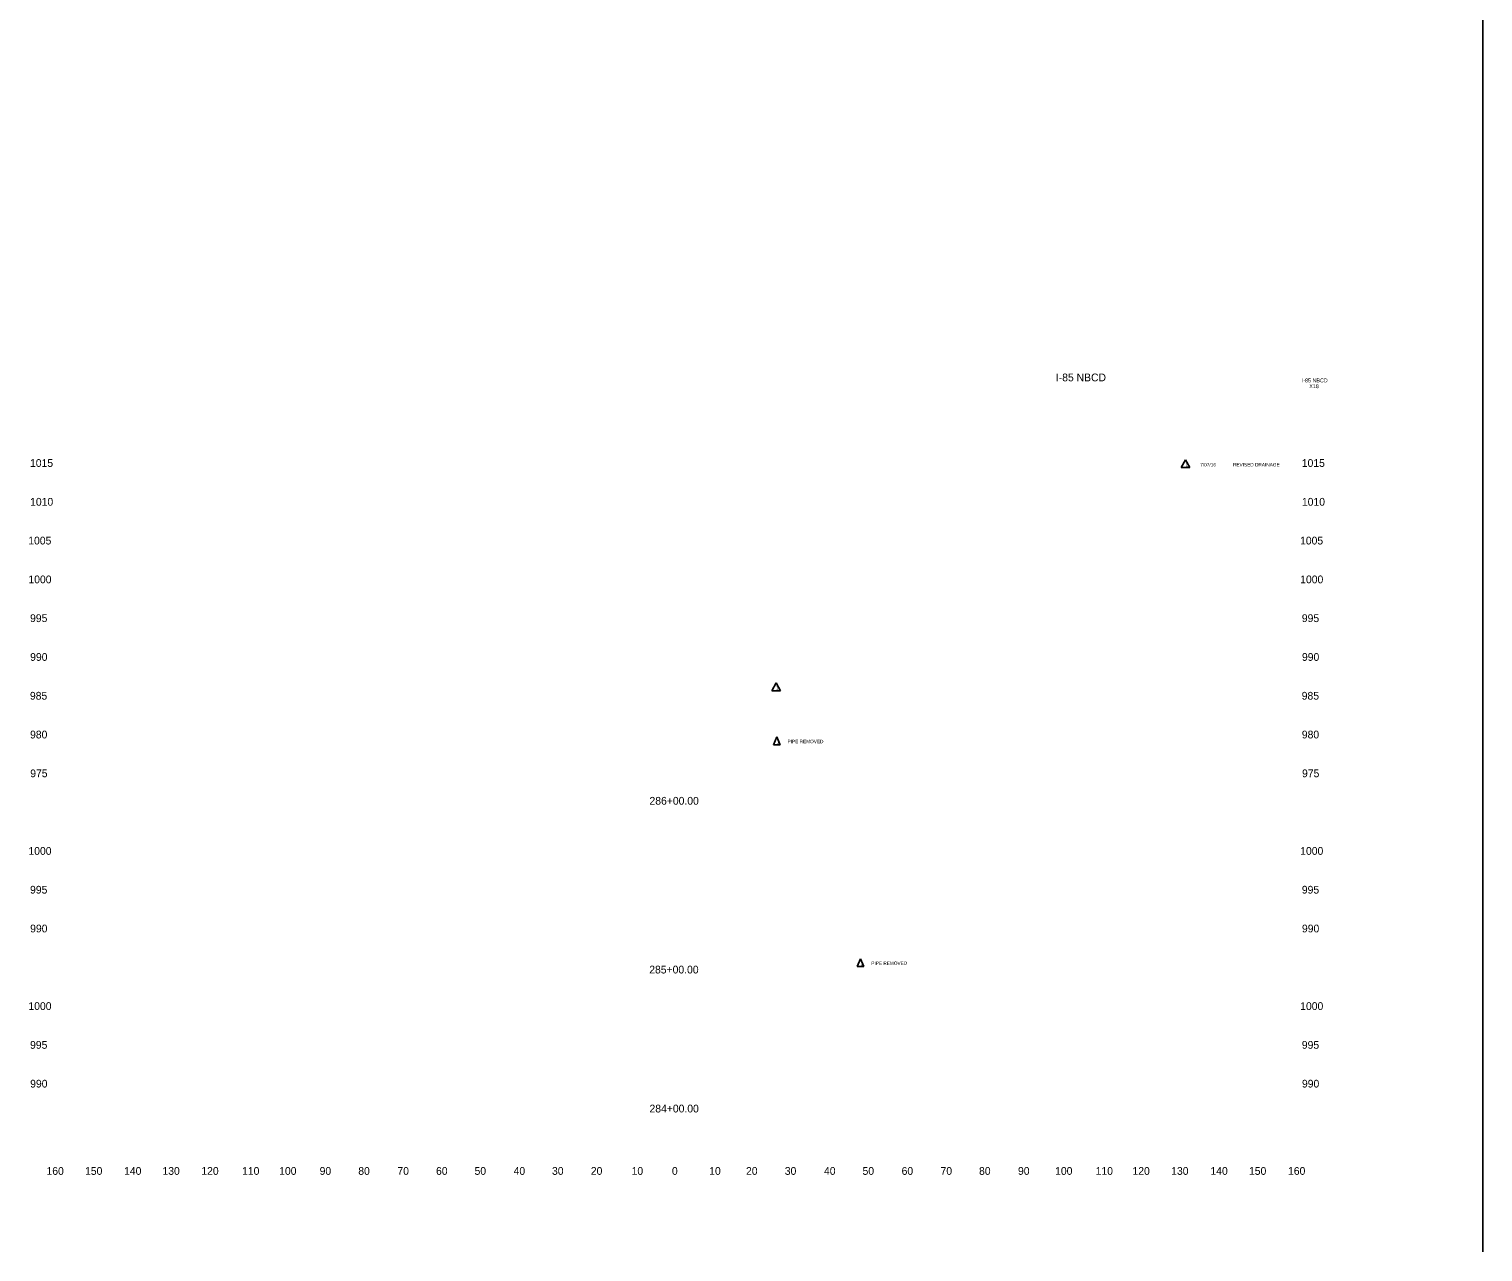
# Model space of a CAD drawing. Extents: x 4994 to 6358, y 4997 to 8804.
# Drawn here: x 5508.6 to 5883.3, y 7777.6 to 8092.9 of the extents above; entities that cross this region are included whole.
import ezdxf

# ---------------------------------------------------------------- set-up
doc = ezdxf.new("R2010")
doc.units = 0
for name, color, linetype in [('RD_SHT_ID', 7, 'Continuous'), ('RD_SHT_TX', 7, 'Continuous'), ('RD_XS_TX_Offset', 7, 'Continuous'), ('RD_XS_TX_Station', 7, 'Continuous')]:
    doc.layers.add(name, color=color, linetype=linetype)

msp = doc.modelspace()

# ---------------------------------------------------------------- linework, layer by layer
at = {"layer": 'RD_SHT_ID'}
msp.add_line((5883.33, 8408.11), (5883.33, 7777.63), dxfattribs=at)
at = {"layer": 'RD_SHT_TX'}
for p, q in [((5806.69, 7981.85), (5805.56, 7979.83)), ((5806.69, 7981.85), (5807.83, 7979.83)), ((5805.56, 7979.83), (5807.83, 7979.83)), ((5701.15, 7924.3), (5700.01, 7922.27)), ((5700.01, 7922.27), (5702.29, 7922.27)), ((5701.15, 7924.3), (5702.29, 7922.27)), ((5701.32, 7910.38), (5700.47, 7908.35)), ((5700.47, 7908.35), (5702.18, 7908.35)), ((5701.32, 7910.38), (5702.18, 7908.35)), ((5722.91, 7853.22), (5722.05, 7851.19)), ((5722.05, 7851.19), (5723.76, 7851.19)), ((5722.91, 7853.22), (5723.76, 7851.19))]:
    msp.add_line(p, q, dxfattribs=at)

# ---------------------------------------------------------------- texts
at = {"layer": 'RD_SHT_ID'}
for s, height, p in [('I-85 NBCD', 2, (5773.26, 8002.06)), ('I-85 NBCD', 1, (5836.65, 8001.8)), ('X18', 1, (5838.57, 8000.3))]:
    msp.add_text(s, height=height, dxfattribs=at).set_placement(p)
at = {"layer": 'RD_SHT_TX'}
for s, p in [('1', (5806.69, 7980.15)), ('7/07/16', (5810.47, 7980.12)), ('REVISED DRAINAGE', (5818.92, 7980.12)), ('1', (5701.15, 7922.6)), ('1', (5701.32, 7908.68)), ('PIPE REMOVED', (5704.11, 7908.77)), ('1', (5722.91, 7851.52)), ('PIPE REMOVED', (5725.69, 7851.61))]:
    msp.add_text(s, height=0.88, dxfattribs=at).set_placement(p)
at = {"layer": 'RD_XS_TX_Offset'}
for s, p in [('1015', (5508.85, 7980)), ('1015', (5836.65, 7980)), ('1010', (5508.88, 7970)), ('1010', (5836.68, 7970)), ('1005', (5508.4, 7960)), ('1005', (5836.2, 7960)), ('1000', (5508.44, 7950)), ('1000', (5836.24, 7950)), ('995', (5508.86, 7940)), ('995', (5836.66, 7940)), ('990', (5508.89, 7930)), ('990', (5836.69, 7930)), ('985', (5508.83, 7920)), ('985', (5836.63, 7920)), ('980', (5508.86, 7910)), ('980', (5836.66, 7910)), ('975', (5508.91, 7900)), ('975', (5836.71, 7900)), ('1000', (5508.44, 7880)), ('1000', (5836.24, 7880)), ('995', (5508.86, 7870)), ('995', (5836.66, 7870)), ('990', (5508.89, 7860)), ('990', (5836.69, 7860)), ('1000', (5508.44, 7840)), ('1000', (5836.24, 7840)), ('995', (5508.86, 7830)), ('995', (5836.66, 7830)), ('990', (5508.89, 7820)), ('990', (5836.69, 7820)), ('160', (5513.1, 7797.5)), ('150', (5523.04, 7797.5)), ('140', (5533.1, 7797.5)), ('130', (5542.99, 7797.5)), ('120', (5553.01, 7797.5)), ('110', (5563.51, 7797.5)), ('100', (5573.07, 7797.5)), ('90', (5583.5, 7797.5)), ('80', (5593.46, 7797.5)), ('70', (5603.54, 7797.5)), ('60', (5613.5, 7797.5)), ('50', (5623.43, 7797.5)), ('40', (5633.5, 7797.5)), ('30', (5643.39, 7797.5)), ('20', (5653.4, 7797.5)), ('10', (5663.91, 7797.5)), ('0', (5674.3, 7797.5)), ('0', (5674.3, 7797.5)), ('10', (5683.91, 7797.5)), ('20', (5693.4, 7797.5)), ('30', (5703.39, 7797.5)), ('40', (5713.5, 7797.5)), ('50', (5723.43, 7797.5)), ('60', (5733.5, 7797.5)), ('70', (5743.54, 7797.5)), ('80', (5753.46, 7797.5)), ('90', (5763.5, 7797.5)), ('100', (5773.07, 7797.5)), ('110', (5783.51, 7797.5)), ('120', (5793.01, 7797.5)), ('130', (5802.99, 7797.5)), ('140', (5813.1, 7797.5)), ('150', (5823.04, 7797.5)), ('160', (5833.1, 7797.5))]:
    msp.add_text(s, height=2, dxfattribs=at).set_placement(p)
at = {"layer": 'RD_XS_TX_Station'}
for s, p in [('286+00.00', (5668.52, 7892.92)), ('285+00.00', (5668.46, 7849.41)), ('284+00.00', (5668.52, 7813.58))]:
    msp.add_text(s, height=2, dxfattribs=at).set_placement(p)

doc.saveas('drawing.dxf')
